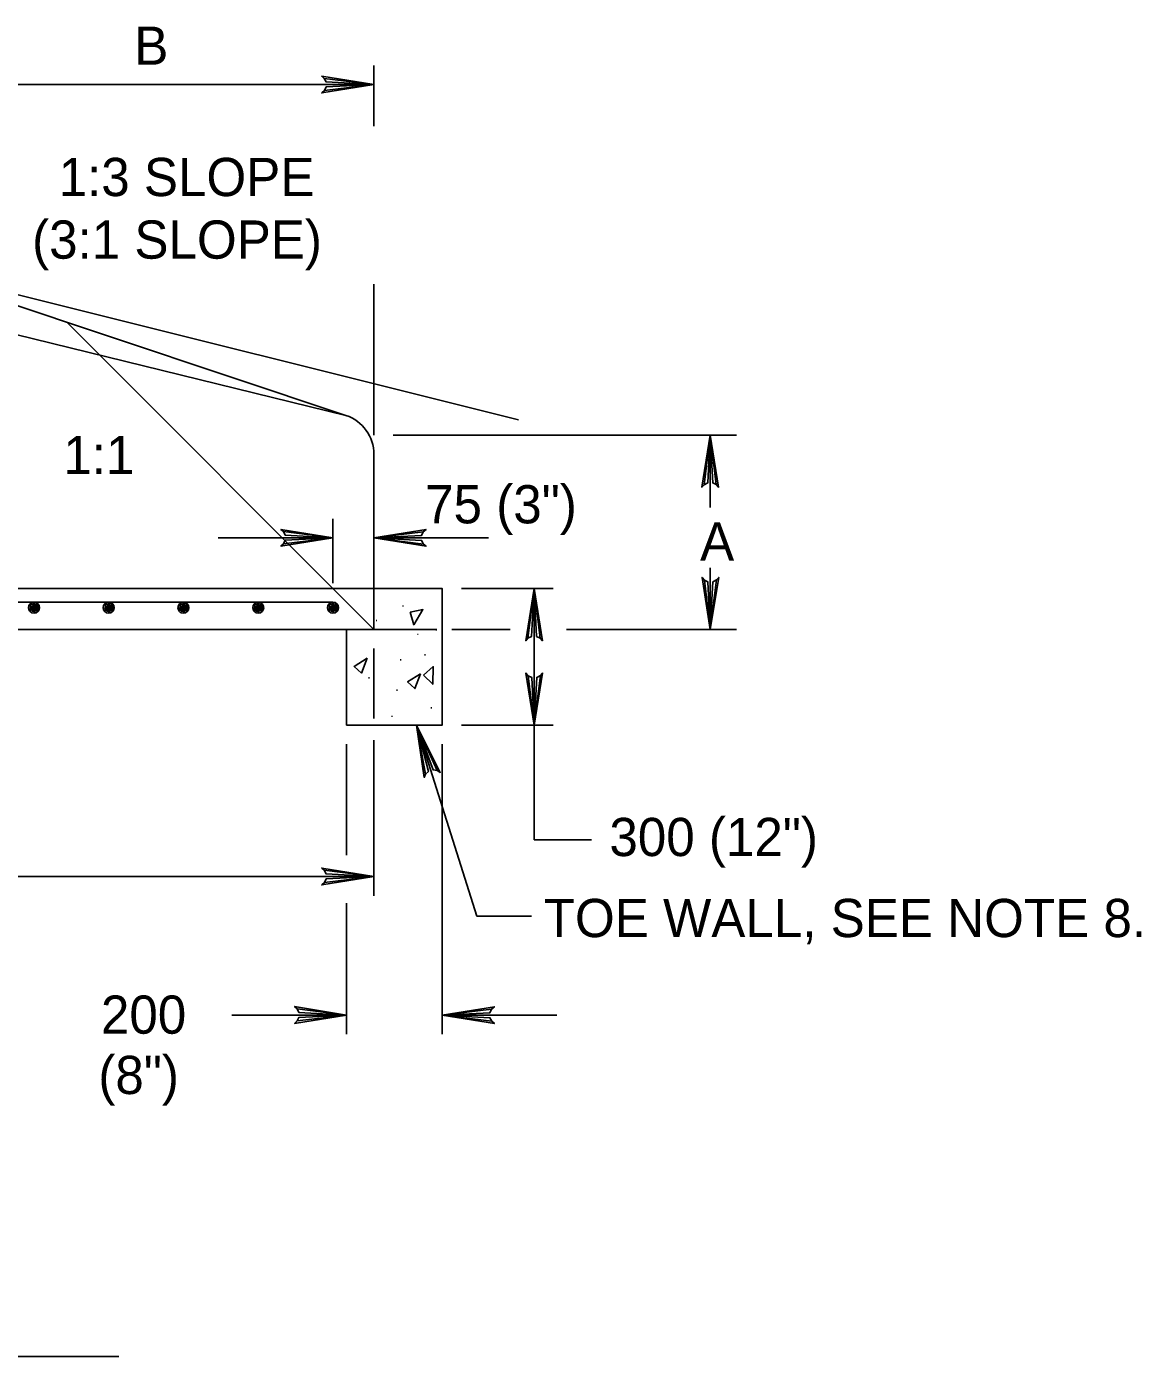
# Model space of a CAD drawing. Extents: x -17 to 888, y -473 to 715.
# Drawn here: x 182.2 to 280.1, y 422 to 538.8 of the extents above; entities that cross this region are included whole.
import ezdxf

# ---------------------------------------------------------------- set-up
doc = ezdxf.new("R2010")
doc.units = 0
doc.layers.add('2', color=7, linetype='Continuous')
doc.layers.add('3', color=7, linetype='Continuous')

msp = doc.modelspace()

# ---------------------------------------------------------------- linework, layer by layer
at = {"layer": '2'}
for p, q in [((212.68, 530.06), (212.68, 535.4)), ((104.28, 534.53), (225.39, 504.25)), ((169.48, 533.72), (200.52, 533.72)), ((200.52, 533.72), (212.68, 533.72)), ((169.48, 518.23), (210.22, 504.65)), ((212.68, 502.91), (212.68, 516.19)), ((210.22, 504.65), (169.48, 514.63)), ((212.68, 485.83), (185.68, 512.83)), ((214.36, 502.91), (244.53, 502.91)), ((242.24, 502.91), (242.24, 496.54)), ((212.68, 485.83), (212.68, 501.23)), ((209.08, 489.91), (209.08, 495.57)), ((212.68, 487.51), (212.68, 495.57)), ((209.08, 493.89), (199, 493.89)), ((212.68, 493.89), (222.76, 493.89)), ((242.24, 491.25), (242.24, 485.83)), ((220.36, 489.43), (228.44, 489.43)), ((226.76, 489.43), (226.76, 477.43)), ((182.41, 487.67), (182.92, 488.15)), ((183.19, 487.94), (182.41, 487.67)), ((182.92, 488.15), (182.46, 488.01)), ((182.51, 487.48), (182.51, 487.94)), ((182.51, 487.94), (182.7, 487.38)), ((182.7, 487.38), (182.73, 488.06)), ((182.73, 488.06), (182.87, 487.35)), ((182.76, 487.35), (183.19, 487.94)), ((183.19, 487.69), (182.76, 487.35)), ((182.81, 488.23), (182.81, 488.23)), ((182.81, 487.75), (182.81, 487.75)), ((182.87, 487.35), (182.84, 488.14)), ((182.84, 488.14), (183.06, 487.44)), ((183.06, 487.44), (183.04, 488.09)), ((183.04, 488.09), (183.19, 487.69)), ((188.98, 487.67), (189.49, 488.15)), ((189.76, 487.94), (188.98, 487.67)), ((189.49, 488.15), (189.02, 488.01)), ((189.08, 487.48), (189.08, 487.94)), ((189.08, 487.94), (189.26, 487.38)), ((189.26, 487.38), (189.3, 488.06)), ((189.3, 488.06), (189.44, 487.35)), ((189.33, 487.35), (189.76, 487.94)), ((189.76, 487.69), (189.33, 487.35)), ((189.37, 488.23), (189.37, 488.23)), ((189.37, 487.75), (189.37, 487.75)), ((189.44, 487.35), (189.41, 488.14)), ((189.41, 488.14), (189.62, 487.44)), ((189.62, 487.44), (189.61, 488.09)), ((189.61, 488.09), (189.76, 487.69)), ((195.54, 487.67), (196.06, 488.15)), ((196.33, 487.94), (195.54, 487.67)), ((196.06, 488.15), (195.59, 488.01)), ((195.64, 487.48), (195.64, 487.94)), ((195.64, 487.94), (195.83, 487.38)), ((195.83, 487.38), (195.87, 488.06)), ((195.87, 488.06), (196, 487.35)), ((195.89, 487.35), (196.33, 487.94)), ((196.33, 487.69), (195.89, 487.35)), ((195.94, 488.23), (195.94, 488.23)), ((195.94, 487.75), (195.94, 487.75)), ((196, 487.35), (195.98, 488.14)), ((195.98, 488.14), (196.19, 487.44)), ((196.19, 487.44), (196.18, 488.09)), ((196.18, 488.09), (196.33, 487.69)), ((202.11, 487.67), (202.62, 488.15)), ((202.9, 487.94), (202.11, 487.67)), ((202.62, 488.15), (202.16, 488.01)), ((202.21, 487.48), (202.21, 487.94)), ((202.21, 487.94), (202.4, 487.38)), ((202.4, 487.38), (202.44, 488.06)), ((202.44, 488.06), (202.57, 487.35)), ((202.46, 487.35), (202.9, 487.94)), ((202.9, 487.69), (202.46, 487.35)), ((202.51, 488.23), (202.51, 488.23)), ((202.51, 487.75), (202.51, 487.75)), ((202.57, 487.35), (202.54, 488.14)), ((202.54, 488.14), (202.76, 487.44)), ((202.76, 487.44), (202.74, 488.09)), ((202.74, 488.09), (202.9, 487.69)), ((208.68, 487.67), (209.19, 488.15)), ((209.47, 487.94), (208.68, 487.67)), ((209.19, 488.15), (208.73, 488.01)), ((208.78, 487.48), (208.78, 487.94)), ((208.78, 487.94), (208.97, 487.38)), ((208.97, 487.38), (209.01, 488.06)), ((209.01, 488.06), (209.14, 487.35)), ((209.03, 487.35), (209.47, 487.94)), ((209.47, 487.69), (209.03, 487.35)), ((209.08, 488.23), (209.08, 488.23)), ((209.08, 487.75), (209.08, 487.75)), ((209.14, 487.35), (209.11, 488.14)), ((209.11, 488.14), (209.33, 487.44)), ((209.33, 487.44), (209.31, 488.09)), ((209.31, 488.09), (209.47, 487.69)), ((61.92, 485.83), (214.36, 485.83)), ((214.36, 485.83), (218.2, 485.83)), ((219.53, 485.83), (224.64, 485.83)), ((229.61, 485.83), (244.53, 485.83)), ((212.68, 484.15), (212.68, 478)), ((220.36, 477.43), (228.44, 477.43)), ((226.76, 467.35), (226.76, 477.43)), ((210.28, 475.75), (210.28, 466.01)), ((212.68, 476.1), (212.68, 462.44)), ((218.68, 475.75), (218.68, 450.27)), ((212.68, 464.12), (178.92, 464.12)), ((210.28, 461.79), (210.28, 450.27)), ((210.28, 451.95), (200.2, 451.95)), ((218.68, 451.95), (228.76, 451.95))]:
    msp.add_line(p, q, dxfattribs=at)
for points in [[(208.32, 534.26), (208.48, 533.95), (212.68, 533.72), (208.32, 534.26), (208.1, 534.45), (212.68, 533.72), (208.48, 533.51), (208.33, 533.2), (212.68, 533.72), (208.1, 532.99), (208.33, 533.2)], [(169.48, 518.23), (126.28, 518.23), (126.28, 485.83), (212.68, 485.83)], [(241.69, 498.56), (242.01, 498.72), (242.24, 502.91), (241.69, 498.56), (241.5, 498.33), (242.24, 502.91), (242.45, 498.72), (242.76, 498.57), (242.24, 502.91), (242.97, 498.33), (242.76, 498.57)], [(204.72, 494.44), (204.88, 494.12), (209.08, 493.89), (204.72, 494.44), (204.5, 494.63), (209.08, 493.89), (204.88, 493.68), (204.73, 493.37), (209.08, 493.89), (204.5, 493.16), (204.73, 493.37)], [(217.04, 493.34), (216.87, 493.66), (212.68, 493.89), (217.04, 493.34), (217.26, 493.15), (212.68, 493.89), (216.87, 494.1), (217.02, 494.41), (212.68, 493.89), (217.26, 494.62), (217.02, 494.41)], [(242.79, 490.19), (242.47, 490.02), (242.24, 485.83), (242.79, 490.19), (242.98, 490.41), (242.24, 485.83), (242.03, 490.02), (241.72, 490.17), (242.24, 485.83), (241.51, 490.41), (241.72, 490.17)], [(128.96, 489.43), (212.68, 489.43)], [(212.68, 485.83), (212.68, 489.43), (218.68, 489.43), (218.68, 477.43), (210.28, 477.43), (210.28, 485.83), (212.68, 485.83)], [(226.21, 485.07), (226.53, 485.23), (226.76, 489.43), (226.21, 485.07), (226.02, 484.85), (226.76, 489.43), (226.97, 485.23), (227.28, 485.08), (226.76, 489.43), (227.49, 484.85), (227.28, 485.08)], [(130.26, 488.23), (209.08, 488.23)], [(227.31, 481.79), (226.99, 481.62), (226.76, 477.43), (227.31, 481.79), (227.5, 482.01), (226.76, 477.43), (226.55, 481.62), (226.24, 481.77), (226.76, 477.43), (226.03, 482.01), (226.24, 481.77)], [(226.53, 460.65), (221.73, 460.65), (216.42, 477.43)], [(217.21, 473.11), (217.47, 473.36), (216.42, 477.43), (217.21, 473.11), (217.1, 472.84), (216.42, 477.43), (217.88, 473.49), (218.23, 473.44), (216.42, 477.43), (218.5, 473.28), (218.23, 473.44)], [(226.76, 467.35), (231.8, 467.35)], [(208.32, 464.67), (208.48, 464.35), (212.68, 464.12), (208.32, 464.67), (208.1, 464.86), (212.68, 464.12), (208.48, 463.91), (208.33, 463.6), (212.68, 464.12), (208.1, 463.39), (208.33, 463.6)], [(205.92, 452.5), (206.08, 452.18), (210.28, 451.95), (205.92, 452.5), (205.7, 452.69), (210.28, 451.95), (206.08, 451.74), (205.93, 451.43), (210.28, 451.95), (205.7, 451.22), (205.93, 451.43)], [(223.04, 451.4), (222.87, 451.72), (218.68, 451.95), (223.04, 451.4), (223.26, 451.21), (218.68, 451.95), (222.87, 452.16), (223.02, 452.47), (218.68, 451.95), (223.26, 452.68), (223.02, 452.47)]]:
    msp.add_lwpolyline(points, dxfattribs=at)
for points in [[(215.87, 487.36), (216.99, 487.59), (216.18, 486.25)], [(212.08, 483.3), (210.93, 482.58), (211.58, 482)], [(216.78, 481.95), (215.63, 481.23), (216.28, 480.64)], [(217.03, 481.83), (217.89, 482.57), (217.85, 481.02)]]:
    msp.add_lwpolyline(points, close=True, dxfattribs=at)
for centre in [(182.81, 487.75), (189.37, 487.75), (195.94, 487.75), (202.51, 487.75), (209.08, 487.75)]:
    msp.add_circle(centre, 0.48, dxfattribs=at)
msp.add_arc((209.08, 501.23), 3.6, 0, 71.5651, dxfattribs=at)
at = {"layer": '3'}
msp.add_line((71.88, 421.95), (190.27, 421.95), dxfattribs=at)

# ---------------------------------------------------------------- texts
at = {"layer": '2'}
for p in [(215.06, 487.83), (215.06, 487.83), (212.74, 486.55), (216.37, 485.34), (217.99, 485.73), (214.85, 483.1), (216.99, 483.53), (212.08, 481.52), (214.54, 480.43), (214.1, 478.13), (217.55, 478.87)]:
    msp.add_text('.', height=0.893, dxfattribs=at).set_placement(p)
at = {"layer": '3'}
for s, p in [('B', (191.62, 535.46)), ('1:3 SLOPE', (184.97, 523.92)), ('(3:1 SLOPE)', (182.64, 518.42)), ('1:1', (185.38, 499.49)), ('75 (3")', (217.18, 495.16)), ('A', (241.34, 491.89)), ('300 (12")', (233.37, 465.92)), ('TOE WALL, SEE NOTE 8.', (227.6, 458.8)), ('200', (188.69, 450.31)), ('(8")', (188.46, 445.01))]:
    msp.add_text(s, height=3.36, dxfattribs=at).set_placement(p)

doc.saveas('drawing.dxf')
